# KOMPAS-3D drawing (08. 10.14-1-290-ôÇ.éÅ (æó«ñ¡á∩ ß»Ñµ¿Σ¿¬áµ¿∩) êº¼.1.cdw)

Views: Вид 1
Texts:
  Текст на чертеже
  Размерные надписи
  Шероховатость
  Линия-выноска #1
  Линия-выноска #2
  Линия-выноска #3
  Отклонения формы и база
  Заголовок таблицы
  Ячейка таблицы
  Стрелка вида
  Обозначение изменения
  Фигурная скобка
  Номер узла
  Марка координационной оси
  VRCB
  Выносная надпись
  Обозначение узла
  Марка/позиционное обозначение с линией-выноской
  Марка/позиционное обозначение на линии
  Марка/позиционное обозначение без линии-выноски
  Состав чартежа
  ячейка табл.
  маркировка
  Маркировка
  Аппараты
  Подпись в квадратике
  ссылки
  цепи
  Без имени
  rustxt
  russ
  Normal
  Лит-Масса-Масштаб
  Материал-Предприятие
  Title Specification
  Body Specification ( left align )
  Body Specificaton ( centered )
  табл
  Additional DXF text style 0
  Обычный
  Термин
  Список определений
  Адрес
  Цитаты
  Форматированный
  Courier New
  Z-конец формы
  Z-начало формы
  Body Text
  ЗОНА_привяз
  txt
  Simplex
  Txt
  heading 1
  Знак Знак Знак Знак Знак Знак
  Verdana
  heading 2
  AGOpus
  footer
  MS Sans Serif
  ТекстШаг1
  Тексты. 3,2
  Body Text 3
  Title
  heading 8
  heading 3
  heading 6
  heading 7
  ООббыыччнныыйй
  ТТееррммиинн
  ССппииссоокк ооппррееддееллеенниийй
  ААддрреесс
  ЦЦииттааттыы
  ФФооррммааттиирроовваанннныыйй
  Z-ккооннеецц ффооррммыы
  Z-ннааччааллоо ффооррммыы
  Абзац Знак
  heading 4
  heading 5
  heading 9
  текст переноса
  клеммы, контакты
  тексты табл
  Table Contents
  Table Heading
  Tahoma
  Денис
  подписи
  Ссылки
  Пояснения
  Definition Term
  Definition List
  Address
  Blockquote
  Preformatted
  z-Bottom of Form
  z-Top of Form
  Клеммник текст
  header
  Текст 3,5
  ГОСТ_МНЕ
  ESK - Обозначение
  Body Text Indent 3
  Основной текст с отступом 3
  TXT
  GOST 2.304 type A
  ISOCP
  style2
  Шрифт 2.5
  Заголовки
  HeliosLight
  Pa3
  Pa1
  RUSTXT
  romanc
  CM12
  romans
  NormalParagraphStyle
  FR5
  Subtitle
  Три с половиной
  eskd1
  Pa15
  Pa18
  терминал
  CNBNDG+TimesNewRoman
  gif
  Пояснения 2
  текст табл
  ISOCPEUR
  CC С?т?и?л?ь? П?о? ц?е?н?т?р?у?
  Adobe Gothic Std B
  Новое оборудование
  .07 RGB_0_0_0 i0b0u0
  Тип, основные технич. данные
  Завод
  изготовитель
  Сигн.
  РЗТ
  Всего
  Автоматические выключатели:
  Лампа светодиодная
  Светильник
  Клеммный блок
  Рабочая крышка
  Кодирующий элемент
  Клеммный ряд в составе:
  Амперметр
  Вольтметр
  Индикация:
  Измерительные приборы:
  Диод
  Выключатель
  Выключатель нагрузки
  Дистанционный расцепитель
  Вспомогательный и сигнальный контакты
  Автоматический выключатель
  СКЛ-11Б-Ж-2-220
  СКЛ-11Б-К-2-220
  IP 44-3 60 Вт/Е27
  KIT KLTR 4TR POCON8
  SD ST 4TR POCON8
  KOEL POCON
  ЩП120П-100мА-220ВУ-
  ЩП120П-110кВ/100В-220ВУ-
  ЩП120П-6кВ/100В-220ВУ-
  PS 4127.000
  OT40F4, Iн=40А
  S282 UC-Z3, 220 В, 3 А
  S282 UC-Z6, 220 В, 6 А
  ОАО "Каскадэлектро"
  Weidmuller
  ОАО "Электроприбор"
  Rittal
  ABB
  АВВ
  Shneider Electric
  Клемма измерительная
  WTL 6/1/STB
  Клемма проходная
  WTD 6/1
  Гнездо
  STB 14
  для
  - винтовой соединительный мостик
  Перемычка:
  Маркировочный шильдик
  Концевой стопор
  Концевая пластина
  Групповой держатель шильдиков
  - соединительная муфта
  - крепежный винт
  Коммутационная аппаратура:
  Кнопка
  Переключатель
  QL 2 SAC6N
  DEK 8
  WEW 35/2
  WAP WTL 6/1
  SchT 5
  QL 4 SAC6N
  QL 6 SAC6N
  VH 12/4.9/3.3 SAC6N
  KISC M3x20 SAC10 CU5
  8LM2T AU120 + 8LM2T B102 +
  + 8LM2T C10
  LOVATO
  APATOR
  Монтажная рейка
  Рамка для надписи малая
  Реле:
  Реле промежуточное
  (двухпозиционное)
  Реле указательное
  Резистор
  TS 35X7.5/LL 1M/ST/ZN
  TS 35X7.5/LL 2M/ST/ZN
  РЭП-38Д-1, постоянного тока,
  РУ 21/0,5, постоянного тока,
  утопленного монтажа
  С5-35В-15-150 Ом 5%
  ОАО "ВНИИР"
  ЗАО "ЧЭАЗ"
  Н.контр
  Разраб.
  Таблицы
  Борисов
  Зам.
  Ведомость покупных изделий
  ГИП
  Микляев
  Н.контр.
  Галкин
  Эксперт
  Ромин
  Лобачёв
  Климов
Dimensions and other numbers on the sheet: 10/14-1-290-УА.ВП; 7; 3,2 (надписи); 2,5 (контакты, клеммы); 3,2_; 2,5; 5_заголовок; 3,2; 3,5_01; 2,5_01; 3,5_tabl; 2,3_; 2,5_3; 3,2_зона не привяз; 3.2 фиол; 2,5 грязносинь; 3.5; 2.5; 1,8; 2.5 курсив; 3,5; 5; 3,2 элементы; 3,2 линия; 3,2 таблица; 3.2 маркировка; 2.5_Э5_надписи; 2.5_Э5_ссылки; 2.5_кабель; 3.2; 2.5 надписи; 3,2 (Зоны); 3.2 (текст); 5,0_белый_подчёркнутый; 5 ШРИФТ; 3 и 5; 0 i0b0u0; 1; 8; 6; 4; 2; 3; 1RS-x-3-0,5; 1N4007; 20; 18; 28; 192; 220; 32; 63; 95; 9; 4G10-66-U-R014; 60; 255; 21; 114; 315; 11; 10; 12; 13; 14; 220 В; 36; 42; 11.12; 11.09/125.003-290-ЭП.ТБ-; 678-13; 08.13; 11.09/125.003-290-ЭП.ВП-; 08.10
